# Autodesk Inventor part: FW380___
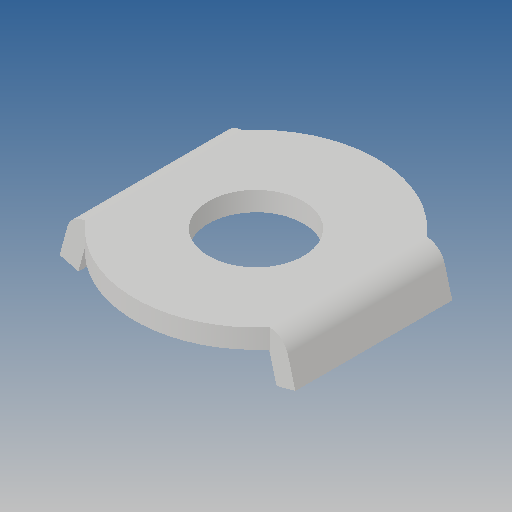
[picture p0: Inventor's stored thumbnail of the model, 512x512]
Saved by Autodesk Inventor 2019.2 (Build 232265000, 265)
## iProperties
Created: 2010-06
Part Number: FW380___
Material: Ogólny
Document SubType Name: Modeling
Designer: CADENGINEERING4
Density: 1 g/cm^3
Appearance: Domyślna
Author: CADENGINEERING4
Revision Number: ANY
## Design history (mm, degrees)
feature "NONE"
node "Bryła1"
